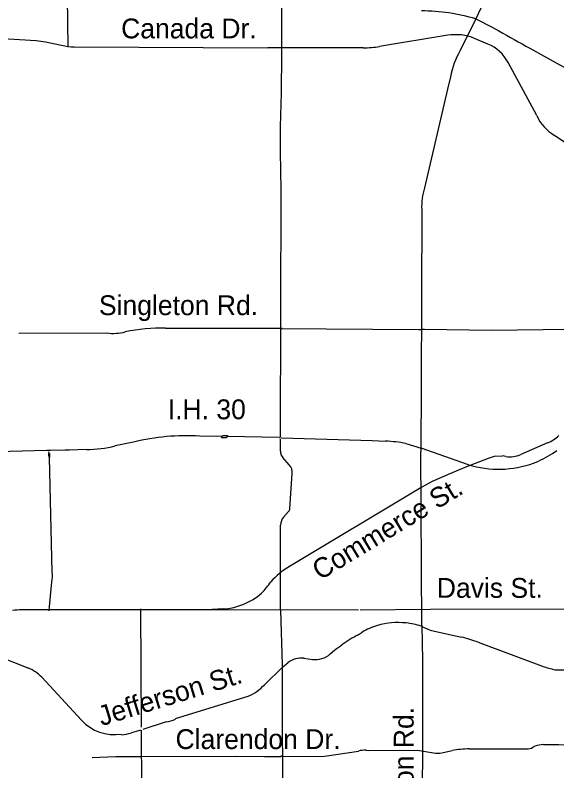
# Model space of a CAD drawing. Extents: x 105094 to 105814, y -291615 to -291123.
# Drawn here: x 105395.2 to 105428.3, y -291494.14 to -291448.01 of the extents above; entities that cross this region are included whole.
import ezdxf

# ---------------------------------------------------------------- set-up
doc = ezdxf.new("R2010")
doc.units = 0
doc.layers.add('G_MAP', color=7, linetype='Continuous')

msp = doc.modelspace()

# ---------------------------------------------------------------- linework, layer by layer
at = {"layer": 'G_MAP'}
for p, q in [((105398.378, -291446.05), (105398.426, -291449.919)), ((105411.486, -291450.371), (105411.489, -291446.767)), ((105423.7, -291447.509), (105423.309, -291448.316)), ((105423.309, -291448.316), (105422.386, -291450.173)), ((105421.629, -291449.237), (105417.471, -291449.919)), ((105394.063, -291449.399), (105396.482, -291449.56)), ((105424.081, -291449.772), (105423.274, -291449.432)), ((105398.816, -291449.944), (105410.633, -291450.006)), ((105416.461, -291449.998), (105410.633, -291450.006)), ((105426.642, -291450.021), (105427.527, -291450.506)), ((105427.527, -291450.506), (105431.537, -291452.737)), ((105427.065, -291454.136), (105425.319, -291450.897)), ((105421.791, -291451.769), (105421.623, -291452.518)), ((105421.623, -291452.518), (105420.219, -291458.557)), ((105429.6, -291456.335), (105428.157, -291455.35)), ((105411.405, -291473.746), (105411.45, -291458.69)), ((105420.038, -291459.859), (105420.009, -291470.629)), ((105404.386, -291467.106), (105411.524, -291467.122)), ((105419.841, -291467.212), (105411.392, -291467.161)), ((105419.983, -291467.212), (105419.837, -291467.212)), ((105420.215, -291467.19), (105420.051, -291467.19)), ((105395.432, -291467.426), (105400.796, -291467.406)), ((105420.009, -291470.629), (105419.989, -291474.643)), ((105402.434, -291474.072), (105401.319, -291474.308)), ((105407.843, -291473.733), (105406.483, -291473.704)), ((105411.334, -291473.791), (105408.146, -291473.736)), ((105411.334, -291473.791), (105411.47, -291473.807)), ((105411.405, -291474.627), (105411.405, -291473.901)), ((105411.47, -291473.807), (105417.018, -291473.981)), ((105417.018, -291473.981), (105417.832, -291474.014)), ((105419.079, -291474.156), (105420.012, -291474.446)), ((105427.734, -291474.107), (105426.095, -291474.828)), ((105397.134, -291474.582), (105393.582, -291474.682)), ((105397.367, -291474.582), (105397.134, -291474.582)), ((105398.261, -291474.556), (105397.367, -291474.582)), ((105398.513, -291474.556), (105398.261, -291474.556)), ((105399.569, -291474.521), (105398.513, -291474.556)), ((105422.889, -291475.454), (105420.012, -291474.446)), ((105428.025, -291474.766), (105428.299, -291474.585)), ((105397.279, -291474.769), (105397.266, -291474.669)), ((105397.464, -291482.003), (105397.292, -291475.015)), ((105411.951, -291475.458), (105411.554, -291475.015)), ((105420.038, -291485.259), (105419.989, -291474.643)), ((105411.986, -291478.115), (105412.134, -291475.99)), ((105422.783, -291475.59), (105421.658, -291476.044)), ((105419.836, -291476.95), (105411.956, -291481.667)), ((105411.605, -291478.647), (105411.904, -291478.308)), ((105411.418, -291484.332), (105411.418, -291479.14)), ((105397.299, -291484.135), (105397.451, -291482.604)), ((105396.863, -291484.316), (105396.151, -291484.303)), ((105406.913, -291484.312), (105397.125, -291484.316)), ((105397.276, -291484.374), (105397.299, -291484.135)), ((105402.87, -291484.248), (105402.905, -291491.475)), ((105407.911, -291484.252), (105406.913, -291484.312)), ((105416.179, -291484.325), (105406.913, -291484.312)), ((105420.577, -291484.284), (105416.285, -291484.325)), ((105438.04, -291484.271), (105420.577, -291484.284)), ((105397.128, -291484.316), (105396.847, -291484.316)), ((105416.166, -291485.827), (105416.395, -291485.683)), ((105420.013, -291485.307), (105420.561, -291485.543)), ((105420.561, -291485.543), (105422.47, -291485.973)), ((105391.273, -291485.988), (105395.983, -291487.853)), ((105423.484, -291486.276), (105427.521, -291487.781)), ((105414.455, -291487.004), (105414.703, -291486.773)), ((105412.849, -291487.267), (105413.36, -291487.338)), ((105410.43, -291488.891), (105411.564, -291487.787)), ((105411.564, -291487.787), (105411.856, -291487.547)), ((105428.286, -291487.981), (105435.853, -291487.978)), ((105396.826, -291488.43), (105399.258, -291491.05)), ((105405.005, -291490.946), (105409.432, -291489.58)), ((105404.43, -291491.156), (105402.996, -291491.611)), ((105402.876, -291491.65), (105402.308, -291491.82)), ((105402.905, -291491.656), (105402.928, -291501.409)), ((105421.26, -291493.032), (105421.895, -291492.906)), ((105422.948, -291492.803), (105426.451, -291492.806)), ((105426.838, -291492.703), (105426.956, -291492.635))]:
    msp.add_line(p, q, dxfattribs=at)
for points in [[(105423.351, -291448.236), (105424.336, -291448.736), (105424.756, -291448.968)], [(105396.482, -291449.56), (105397.06, -291449.628), (105398.042, -291449.844)], [(105411.45, -291458.69), (105411.411, -291456.336), (105411.412, -291454.834), (105411.47, -291452.744), (105411.486, -291450.371)], [(105434.964, -291467.178), (105432.187, -291467.157), (105424.304, -291467.257), (105420.212, -291467.19)], [(105425.174, -291474.948), (105424.982, -291474.918), (105424.953, -291474.921), (105424.459, -291474.953), (105424.091, -291475.079), (105422.783, -291475.59)], [(105411.418, -291484.332), (105411.509, -291487.671), (105411.548, -291507.862)], [(105420.038, -291485.259), (105420.086, -291487.387), (105420.086, -291491.595), (105420.048, -291501.487), (105420.061, -291510.045), (105420.113, -291518.574), (105420.181, -291527.093)], [(105427.482, -291492.532), (105428.412, -291492.528), (105429.612, -291492.597)], [(105411.548, -291493.262), (105414.102, -291493.239), (105416.175, -291492.929)], [(105416.637, -291492.883), (105416.77, -291492.9), (105419.786, -291492.871), (105420.766, -291493.038)], [(105399.917, -291493.324), (105401.326, -291493.273), (105402.879, -291493.27), (105408.66, -291493.251), (105410.436, -291493.267), (105411.434, -291493.267)]]:
    msp.add_lwpolyline(points, dxfattribs=at)
msp.add_lwpolyline([(105407.881, -291473.664), (105408.185, -291473.667), (105408.108, -291473.805), (105407.805, -291473.802)], close=True, dxfattribs=at)
for centre, radius, start, end in [((105419.971, -291459.637), 11.891, 73.4855, 89.7536), ((105422.113, -291452.189), 2.991, 67.1674, 99.3073), ((105483.409, -291346.104), 118.411, 240.30829, 241.35345), ((105398.817, -291446.897), 3.048, 255.2693, 269.9888), ((105416.493, -291443.947), 6.051, 269.6969, 279.3021), ((105423.105, -291452.091), 2.515, 28.3361, 67.1679), ((105427.133, -291452.85), 5.45, 150.5838, 168.5558), ((105429.518, -291453.028), 2.691, 204.2964, 239.6127), ((105423.759, -291459.712), 3.724, 161.9268, 182.2497), ((105404.357, -291479.685), 12.579, 89.8649, 101.1086), ((105401.2, -291464.479), 2.955, 262.1446, 284.3594), ((105405.676, -291487.278), 13.598, 86.5949, 103.7932), ((105427.069, -291472.308), 1.918, 290.2692, 314.4275), ((105417.537, -291482.142), 8.133, 79.0741, 87.9215), ((105399.569, -291467.222), 7.298, 270.004, 283.8807), ((105397.601, -291474.752), 0.365, 183.0131, 202.6938), ((105396.928, -291475.034), 0.365, 3.013, 22.6937), ((105397.657, -291474.996), 0.365, 163.3324, 183.0131), ((105396.958, -291474.786), 0.365, 343.3323, 3.013), ((105411.987, -291474.627), 0.582, 180.0111, 221.9106), ((105425.43, -291473.315), 1.653, 261.1185, 293.739), ((105424.785, -291469.858), 5.881, 290.8436, 303.4278), ((105411.416, -291475.939), 0.719, 355.9122, 41.9488), ((105424.732, -291469.358), 6.369, 253.184, 289.6927), ((105426.553, -291488.17), 13.077, 111.9829, 120.9064), ((105411.659, -291478.091), 0.327, 318.5044, 355.8586), ((105412.163, -291479.14), 0.745, 138.5391, 180.0011), ((105395.22, -291482.256), 2.257, 351.122, 6.417), ((105414.474, -291485.874), 4.903, 120.9086, 138.123), ((105406.35, -291479.502), 5.442, 315.9539, 325.2895), ((105407.685, -291480.361), 3.898, 273.3185, 311.384), ((105395.983, -291493.041), 8.74, 88.8991, 96.1409), ((105418.626, -291489.877), 4.789, 84.4602, 105.6417), ((105418.518, -291490.07), 4.992, 72.5785, 83.4424), ((105418.318, -291488.743), 3.614, 105.7852, 122.1496), ((105421.077, -291494.996), 10.401, 118.1775, 124.6646), ((105410.704, -291527.121), 42.798, 72.6259, 74.0431), ((105411.821, -291482.318), 5.306, 302.8938, 309.0142), ((105413.632, -291486.122), 1.207, 284.4996, 312.9871), ((105412.672, -291488.539), 1.285, 82.0724, 129.4393), ((105413.541, -291486.035), 1.315, 262.0979, 287.3989), ((105395.132, -291490.002), 2.311, 42.8625, 68.4061), ((105428.991, -291483.725), 4.314, 250.0792, 260.6012), ((105408.471, -291487.12), 2.64, 291.3392, 317.8921), ((105401.281, -291489.167), 2.764, 222.9609, 278.3279), ((105403.488, -291486.864), 4.393, 282.3759, 290.1917), ((105401.323, -291488.513), 3.45, 276.1231, 286.5905), ((105427.626, -291494.658), 2.132, 93.8779, 108.3354), ((105416.58, -291494.684), 1.801, 88.1874, 102.9913), ((105420.996, -291491.698), 1.36, 260.2772, 281.2272), ((105422.942, -291498.179), 5.376, 89.936, 101.2326), ((105426.451, -291492.03), 0.776, 269.9738, 299.9444), ((105411.547, -291493.115), 0.147, 220.0156, 270.4557)]:
    msp.add_arc(centre, radius, start, end, dxfattribs=at)

# ---------------------------------------------------------------- texts
for s, height, p in [('Canada Dr.', 1.2111, (105401.677, -291449.426)), ('Singleton Rd.', 1.21107, (105400.32, -291466.321)), ('I.H. 30', 1.2111, (105404.525, -291472.676)), ('Davis St.', 1.2111, (105420.963, -291483.578)), ('Clarendon Dr.', 1.21107, (105405.003, -291492.809))]:
    msp.add_text(s, height=height, dxfattribs=at).set_placement(p)
for s, rotation, p in [('Commerce St.', 31.2511, (105413.826, -291482.535)), ('Jefferson St.', 17.128, (105400.482, -291491.417)), ('Hampton Rd.', 90, (105419.546, -291499.777))]:
    msp.add_text(s, height=1.21107, rotation=rotation, dxfattribs=at).set_placement(p)

doc.saveas('drawing.dxf')
